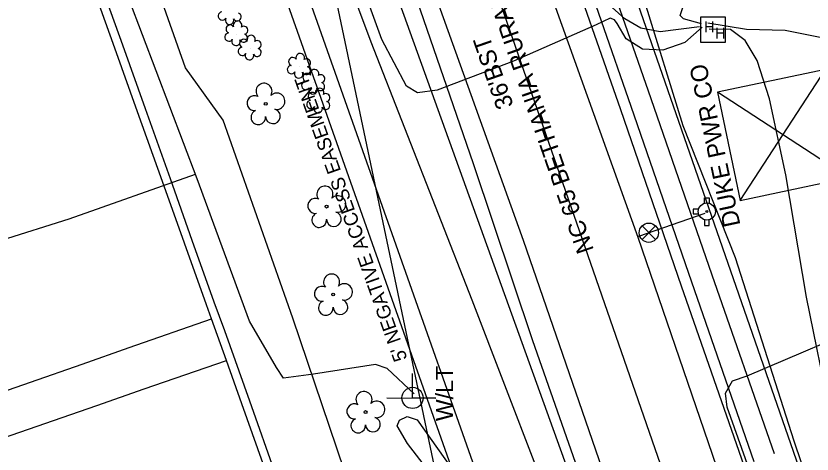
# Model space of a CAD drawing. Extents: x 1614611 to 1617571, y 898867 to 905462.
# Drawn here: x 1616147.3 to 1616331.4, y 903736.2 to 903837.4 of the extents above; entities that cross this region are included whole.
import ezdxf

# ---------------------------------------------------------------- set-up
doc = ezdxf.new("R2010")
doc.units = 0
for name, color, linetype in [('Exist Boundary Watershed Residential C 05', 7, 'Continuous'), ('Exist Other Culture Fence Line', 7, 'Continuous'), ('Exist Right of Way Easement Line Text', 7, 'Continuous'), ('Exist Roads Change in Surface', 7, 'Continuous'), ('Exist Roads EOP Text', 7, 'Continuous'), ('Exist Utilities Gas UG Line SUE LOS B', 7, 'Continuous'), ('Exist Utilities Power Joint Use Telephone CELL', 7, 'Continuous'), ('Exist Utilities Power Joint Use Telephone Text', 7, 'Continuous'), ('Exist Utilities Power Tower Text', 7, 'Continuous'), ('Exist Utilities Telephone Hand Hole CELL', 7, 'Continuous'), ('Exist Utilities Telephone UG Cable SUE LOS B', 7, 'Continuous'), ('Exist Utilities Telephone UG FO SUE LOS B', 7, 'Continuous'), ('Exist Utilities Telephone UG FO SUE LOS C', 7, 'Continuous'), ('Exist Utilities Water UG Line SUE LOS B', 7, 'Continuous'), ('Exist Vegetation Hedge Row', 7, 'Continuous'), ('Exist Vegetation Shrub CELL', 7, 'Continuous'), ('Exist Vegetation Tree CELL', 7, 'Continuous'), ('Prop Drainage Structure Catch Basin Grate 840 03E Label', 7, 'Continuous'), ('Prop Drainage Structure Drop Inlet In Approach Slab 840 13 CELL', 7, 'Continuous'), ('Prop Earthen Structure Base Ditch Detail CELL', 7, 'Continuous'), ('Prop Earthen Structure Cut Ditch Special Back of Curb Detail CELL', 7, 'Continuous'), ('Prop Earthen Structure Head Ditch Label', 7, 'Continuous'), ('Prop Earthen Structure V Ditch Detail Label', 7, 'Continuous'), ('Raster_Level_2', 7, 'Continuous'), ('Scratch_Level_1', 7, 'Continuous'), ('Scratch_Level_9', 7, 'Continuous')]:
    doc.layers.add(name, color=color, linetype=linetype)

# ---------------------------------------------------------------- blocks, each defined once
blk = doc.blocks.new('EXIST UTILITIES WATER FIRE HYDRANT')
at = {"layer": 'Prop Earthen Structure Base Ditch Detail CELL'}
blk.add_line((0, 0), (0, 0), dxfattribs=at)
for points in [[(-0.01025, 0.03825), (-0.01025, 0.064), (0.01025, 0.064), (0.01025, 0.03775)], [(-0.03825, 0.01025), (-0.064, 0.01025), (-0.064, -0.01025), (-0.03825, -0.01025)], [(-0.01025, -0.03825), (-0.01025, -0.064), (0.01025, -0.064), (0.01025, -0.03775)]]:
    blk.add_lwpolyline(points, dxfattribs=at)
for radius in [0.03954, 0.00485]:
    blk.add_circle((0, 0), radius, dxfattribs=at)
blk = doc.blocks.new('EXIST UTILITIES WATER VALVE')
at = {"layer": 'Prop Earthen Structure V Ditch Detail Label'}
blk.add_lwpolyline([(0.0315, 0.0315), (-0.0315, -0.0315), (0, 0), (0.0315, -0.0315), (-0.0315, 0.0315)], dxfattribs=at)
blk.add_circle((0, 0), 0.0445, dxfattribs=at)

msp = doc.modelspace()

# ---------------------------------------------------------------- linework, layer by layer
at = {"layer": 'Exist Boundary Watershed Residential C 05'}
for points in [[(1616117.86, 904294.32), (1616132.6, 904254.66), (1616147.03, 904215.59), (1616161.55, 904176.09), (1616175.82, 904137.25), (1616190.47, 904097.09), (1616204.98, 904057.33), (1616219.73, 904016.73), (1616233.88, 903976.63), (1616247.93, 903936.53), (1616261.75, 903896.6), (1616275.82, 903856.12), (1616289.5, 903816.57), (1616303.58, 903775.98), (1616318, 903734.48)], [(1616195.63, 903764.68), (1616193.18, 903771.3), (1616188.12, 903785.57), (1616183.07, 903799.8), (1616177.32, 903815.93), (1616172.04, 903830.68), (1616166.62, 903845.72)], [(1616228.55, 903499.67), (1616241.49, 903504.21), (1616254.35, 903508.75), (1616274.1, 903515.89), (1616283.18, 903519.23), (1616278.16, 903533.55), (1616272.29, 903550.22), (1616266.96, 903564.82), (1616261.52, 903580.04), (1616256.36, 903594.89), (1616250.78, 903610.5), (1616245.15, 903626.51), (1616239.64, 903641.51), (1616233.87, 903657.61), (1616228.87, 903671.59), (1616223.77, 903685.94), (1616218.3, 903701.18), (1616213.09, 903715.7), (1616207.52, 903731.14), (1616201.4, 903748.42), (1616195.63, 903764.68)]]:
    msp.add_lwpolyline(points, dxfattribs=at)
at = {"layer": 'Exist Other Culture Fence Line'}
for points in [[(1616211.35, 903767.58), (1616195.22, 903813.36), (1616186.56, 903825.42), (1616168.75, 903875.81), (1616153.63, 903916.5), (1616129.58, 903932.3), (1616098.05, 903952.43), (1616082.04, 903962.19), (1616045.01, 903949.52), (1616000.86, 903933.41), (1615934.86, 903910.4), (1615905.89, 903899.71)], [(1616340.29, 903264.26), (1616332.08, 903290.24), (1616316.67, 903338.32), (1616302.47, 903379.06), (1616267.37, 903366.34), (1616220.02, 903349.18), (1616202.8, 903398.78), (1616185.25, 903447.61), (1616177.66, 903469.59), (1616182.75, 903471.48), (1616219.13, 903484.56), (1616299.32, 903513.96), (1616290.54, 903538.93), (1616272.63, 903588.03), (1616251.39, 903649.78), (1616231.78, 903707.31), (1616211.35, 903767.58)]]:
    msp.add_lwpolyline(points, dxfattribs=at)
at = {"layer": 'Exist Roads Change in Surface'}
for points in [[(1615977.86, 903692.4), (1616012.69, 903704.67), (1616058.14, 903720.5), (1616081.62, 903728.6), (1616102.28, 903735.77), (1616138.67, 903748.68), (1616162.62, 903756.97), (1616173.49, 903760.81), (1616192.57, 903767.41)], [(1615981.36, 903682.64), (1616016.19, 903695.14), (1616061.6, 903710.95), (1616085.09, 903719.1), (1616105.67, 903726.37), (1616142.12, 903739.16), (1616166.07, 903747.45), (1616176.95, 903751.26), (1616196.01, 903757.85)]]:
    msp.add_lwpolyline(points, dxfattribs=at)
at = {"layer": 'Exist Utilities Gas UG Line SUE LOS B'}
msp.add_lwpolyline([(1616574.94, 902856.71), (1616560.06, 902902.39), (1616552.18, 902925.27), (1616536.08, 902973.65), (1616521.52, 903015.88), (1616492.41, 903100.65), (1616481.17, 903130.4), (1616470.48, 903162.66), (1616450.18, 903220.6), (1616431.22, 903276.51), (1616418.49, 903313.39), (1616364.61, 903464.71), (1616350.51, 903509.73), (1616310.55, 903618.21), (1616275.13, 903713.81), (1616252.85, 903771.73), (1616229.48, 903831.39), (1616218.51, 903860.65), (1616218.15, 903861.58), (1616200.49, 903922.94), (1616158.51, 904013.15), (1616156.79, 904018.63), (1616125.02, 904117.19), (1616112.76, 904150.51)], dxfattribs=at)
at = {"layer": 'Exist Utilities Power Joint Use Telephone CELL'}
msp.add_line((1616239.05, 903749.18), (1616239.05, 903749.18), dxfattribs=at)
msp.add_lwpolyline([(1616233.11, 903749.18), (1616244.45, 903749.14), (1616239.05, 903749.16), (1616239.05, 903754.8)], dxfattribs=at)
msp.add_circle((1616239.05, 903749.18), 2.45, dxfattribs=at)
at = {"layer": 'Exist Utilities Telephone Hand Hole CELL'}
for p, q in [((1616305.68, 903837.13), (1616305.68, 903831.4)), ((1616311.41, 903837.13), (1616305.68, 903837.13)), ((1616311.41, 903831.4), (1616311.41, 903837.13)), ((1616308.55, 903834.26), (1616308.55, 903834.26)), ((1616305.68, 903831.4), (1616311.41, 903831.4))]:
    msp.add_line(p, q, dxfattribs=at)
at = {"layer": 'Exist Utilities Telephone UG Cable SUE LOS B'}
for points in [[(1616341.13, 903526.17), (1616350.06, 903524.57), (1616353.18, 903523.97), (1616354.27, 903525.62), (1616354.2, 903527.32), (1616352.41, 903531.49), (1616346.51, 903551.88), (1616338.38, 903572.73), (1616311.12, 903649.59), (1616299.64, 903684.42), (1616264.73, 903785.56), (1616225.23, 903895.34)], [(1616373.87, 903568.46), (1616374.3, 903569.41), (1616373.86, 903570.39), (1616361.62, 903602.86), (1616341.95, 903659.09), (1616330.11, 903695.59), (1616311.83, 903747.03), (1616311.46, 903750.28), (1616313.05, 903753.14), (1616316.41, 903754.31), (1616347.19, 903767.38), (1616362.66, 903772.42), (1616371.42, 903776.41)]]:
    msp.add_lwpolyline(points, dxfattribs=at)
at = {"layer": 'Exist Utilities Telephone UG FO SUE LOS B'}
for points in [[(1616305.86, 903835.58), (1616301.71, 903836.75), (1616300.93, 903837.51), (1616301.7, 903839.81), (1616304.58, 903843.5), (1616306.34, 903849.92), (1616306.68, 903889.95), (1616304.63, 903908.72), (1616293.63, 903957.65), (1616274.72, 904023.16), (1616260.11, 904069.82), (1616245.31, 904104.27), (1616231.41, 904145.88), (1616215.41, 904195.22), (1616204.68, 904240.22), (1616199.33, 904261.21), (1616183.55, 904304.43), (1616162.6, 904355.73), (1616148.58, 904401.99), (1616136.38, 904433.35), (1616120.49, 904476.41), (1616105.61, 904520.44), (1616089.41, 904571.33)], [(1616305.43, 903834.95), (1616296.33, 903833.77), (1616291.87, 903834.62), (1616288.13, 903836.73), (1616285.25, 903839.39), (1616277.28, 903853.64), (1616262.51, 903895.33), (1616243.28, 903949.17), (1616237.33, 903966.37), (1616227.47, 903998.34)], [(1616306.02, 903834.81), (1616302.03, 903831.29), (1616296.93, 903829.49), (1616292.25, 903829.78), (1616288.46, 903832.16), (1616286.38, 903835.67), (1616285.77, 903836.54), (1616284.73, 903836.89), (1616281.51, 903835.36), (1616262.41, 903826.99), (1616244.75, 903820.26), (1616240.16, 903819.66), (1616237.67, 903821.17), (1616231.95, 903831.99), (1616208.49, 903896.38)], [(1616413.77, 903500.18), (1616402.08, 903534.75), (1616383.28, 903584.85), (1616378.31, 903598.68), (1616360.02, 903639.24), (1616356.39, 903655.99), (1616340.68, 903699.57), (1616327.33, 903739.18), (1616327.34, 903739.18), (1616313.72, 903781.55), (1616301.65, 903812.03), (1616292.8, 903840.69)], [(1616307.37, 903835.83), (1616316.28, 903834.41), (1616325.26, 903834.16), (1616333.69, 903832.44), (1616339.08, 903829.17), (1616355.03, 903804.45), (1616367.18, 903789.49), (1616372.35, 903777.82)], [(1616367.72, 903663.9), (1616363.6, 903662.09), (1616361.25, 903662.79), (1616358.51, 903666.15), (1616344.89, 903713.16), (1616335.76, 903744.87), (1616330.15, 903772.43), (1616325.41, 903800.74), (1616321.6, 903818.31), (1616318.76, 903827.11), (1616315.94, 903831.79), (1616312.59, 903834.29), (1616307.67, 903834.34)]]:
    msp.add_lwpolyline(points, dxfattribs=at)
at = {"layer": 'Exist Utilities Telephone UG FO SUE LOS C'}
msp.add_lwpolyline([(1616279.08, 903721.31), (1616179.5, 903997.15), (1616170.18, 904002.27)], dxfattribs=at)
at = {"layer": 'Exist Utilities Water UG Line SUE LOS B'}
msp.add_line((1616306.62, 903791.8), (1616291.31, 903786.5), dxfattribs=at)
msp.add_lwpolyline([(1616526.94, 903118.95), (1616504.59, 903181.23), (1616480.02, 903252.46), (1616446.17, 903345), (1616411.28, 903445.17), (1616385.62, 903515.15), (1616350.02, 903616.87), (1616323.73, 903691.37), (1616291.21, 903786.26), (1616260.45, 903872.07), (1616224.66, 903974.02), (1616192.08, 904066.13), (1616173.94, 904118.11), (1616130.42, 904237.78), (1616097.26, 904331.65), (1616083.48, 904374.45), (1616069.85, 904420.53), (1616059.14, 904458.49), (1616050.85, 904496.39), (1616045.84, 904527.76), (1616030.28, 904669.9)], dxfattribs=at)
at = {"layer": 'Exist Vegetation Hedge Row'}
msp.add_lwpolyline([(1616244.1, 903730.53), (1616237.85, 903738.68), (1616235.5, 903742.71), (1616236, 903744), (1616237.79, 903744.91), (1616240.15, 903744.1), (1616247.84, 903733.22)], dxfattribs=at)
at = {"layer": 'Exist Vegetation Shrub CELL'}
for p, q in [((1616198.36, 903833.24), (1616198.36, 903833.24)), ((1616201.48, 903829.93), (1616201.48, 903829.93)), ((1616212.84, 903825.73), (1616212.84, 903825.73)), ((1616216.15, 903822.05), (1616216.15, 903822.05)), ((1616217.33, 903817.68), (1616217.33, 903817.68))]:
    msp.add_line(p, q, dxfattribs=at)
for centre, radius, start, end in [((1616195.06, 903837.42), 0.955, 95.1099, 327.9534), ((1616198.5, 903837.19), 0.937, 204.9913, 73.4601), ((1616196.73, 903836.44), 0.984, 151.2797, 21.387), ((1616198.59, 903835.28), 0.99, 334.8391, 200.4717), ((1616196.88, 903834.37), 0.968, 35.8908, 245.4216), ((1616200.03, 903834.11), 0.929, 284.4567, 126.0861), ((1616196.56, 903832.54), 0.955, 95.1099, 327.9534), ((1616200, 903832.31), 0.937, 204.9913, 73.4601), ((1616201.71, 903831.97), 0.99, 334.8391, 200.4717), ((1616198.23, 903831.56), 0.984, 151.2797, 21.387), ((1616200, 903831.06), 0.968, 35.8908, 245.4216), ((1616203.15, 903830.8), 0.929, 284.4567, 126.0861), ((1616199.68, 903829.23), 0.955, 95.1099, 327.9534), ((1616203.12, 903829), 0.937, 204.9913, 73.4601), ((1616201.35, 903828.25), 0.984, 151.2797, 21.387), ((1616211.36, 903826.86), 0.968, 35.8908, 245.4216), ((1616213.07, 903827.77), 0.99, 334.8391, 200.4717), ((1616214.51, 903826.6), 0.929, 284.4567, 126.0861), ((1616211.04, 903825.03), 0.955, 95.1099, 327.9534), ((1616214.48, 903824.8), 0.937, 204.9913, 73.4601), ((1616212.71, 903824.05), 0.984, 151.2797, 21.387), ((1616214.67, 903823.18), 0.968, 35.8908, 245.4216), ((1616216.38, 903824.09), 0.99, 334.8391, 200.4717), ((1616217.83, 903822.92), 0.929, 284.4567, 126.0861), ((1616214.35, 903821.35), 0.955, 95.1099, 327.9534), ((1616217.79, 903821.12), 0.937, 204.9913, 73.4601), ((1616215.85, 903818.81), 0.968, 35.8908, 245.4216), ((1616216.03, 903820.37), 0.984, 151.2797, 21.387), ((1616217.56, 903819.72), 0.99, 334.8391, 200.4717), ((1616215.53, 903816.98), 0.955, 95.1099, 327.9534), ((1616219.01, 903818.55), 0.929, 284.4567, 126.0861), ((1616217.21, 903816), 0.984, 151.2797, 21.387), ((1616218.97, 903816.76), 0.937, 204.9913, 73.4601)]:
    msp.add_arc(centre, radius, start, end, dxfattribs=at)
at = {"layer": 'Exist Vegetation Tree CELL'}
for p, q in [((1616205.09, 903817.14), (1616205.09, 903817.14)), ((1616219.18, 903793.38), (1616219.18, 903793.38)), ((1616220.71, 903773.07), (1616220.71, 903773.07)), ((1616228.2, 903745.92), (1616228.2, 903745.92))]:
    msp.add_line(p, q, dxfattribs=at)
for centre in [(1616205.09, 903817.14), (1616219.18, 903793.38), (1616220.71, 903773.07), (1616228.2, 903745.92)]:
    msp.add_circle(centre, 0.326, dxfattribs=at)
for centre, radius, start, end in [((1616204.71, 903820.01), 1.86, 330.1651, 219.7134), ((1616207.64, 903817.72), 1.9, 257.1011, 134.1999), ((1616202.48, 903817.29), 1.73, 62.6636, 279.3457), ((1616203.39, 903814.01), 1.69, 111.5671, 6.231), ((1616206.76, 903814.24), 1.7, 181.2822, 74.56), ((1616218.79, 903796.25), 1.86, 330.1651, 219.7134), ((1616221.73, 903793.96), 1.9, 257.1011, 134.1999), ((1616216.57, 903793.53), 1.73, 62.6636, 279.3457), ((1616220.85, 903790.48), 1.7, 181.2822, 74.56), ((1616217.47, 903790.25), 1.69, 111.5671, 6.231), ((1616220.32, 903775.94), 1.86, 330.1651, 219.7134), ((1616223.26, 903773.66), 1.9, 257.1011, 134.1999), ((1616218.1, 903773.22), 1.73, 62.6636, 279.3457), ((1616222.38, 903770.17), 1.7, 181.2822, 74.56), ((1616219, 903769.95), 1.69, 111.5671, 6.231), ((1616227.82, 903748.79), 1.86, 330.1651, 219.7134), ((1616225.6, 903746.07), 1.73, 62.6636, 279.3457), ((1616230.75, 903746.51), 1.9, 257.1011, 134.1999), ((1616226.5, 903742.8), 1.69, 111.5671, 6.231), ((1616229.88, 903743.02), 1.7, 181.2822, 74.56)]:
    msp.add_arc(centre, radius, start, end, dxfattribs=at)
at = {"layer": 'Prop Drainage Structure Catch Basin Grate 840 03E Label'}
for points in [[(1616216.11, 903754.65), (1616209.18, 903753.77), (1616207.59, 903756.18), (1616201.31, 903766.89), (1616189.22, 903799.82), (1616173.47, 903841.46), (1616167.39, 903860.41), (1616167.16, 903861.99), (1616154.51, 903899.58), (1616149.01, 903912.2)], [(1616188.81, 903800.81), (1616159.54, 903790.47), (1616143.92, 903785.53), (1616125.62, 903780.42), (1616107.73, 903774.01), (1616106.42, 903773.68), (1616075.03, 903763.65), (1616039.24, 903750.83), (1616002.72, 903737.28), (1615981.14, 903729.78)], [(1616239.41, 903750.09), (1616233.18, 903755.96), (1616230.51, 903756.88), (1616216.11, 903754.65)]]:
    msp.add_lwpolyline(points, dxfattribs=at)
at = {"layer": 'Prop Drainage Structure Drop Inlet In Approach Slab 840 13 CELL'}
msp.add_lwpolyline([(1616314.85, 903794.79), (1616339.85, 903800.09), (1616334.54, 903825.08), (1616309.55, 903819.78), (1616314.85, 903794.79), (1616334.54, 903825.08), (1616339.85, 903800.09), (1616309.55, 903819.78)], dxfattribs=at)
at = {"layer": 'Prop Earthen Structure Cut Ditch Special Back of Curb Detail CELL'}
msp.add_lwpolyline([(1616323.1, 903521.01), (1616157.44, 903989.53)], dxfattribs=at)
at = {"layer": 'Prop Earthen Structure Head Ditch Label'}
msp.add_line((1615887.44, 905426.15), (1616864.55, 900788.06), dxfattribs=at)
for points in [[(1616327.81, 903522.67), (1616162.16, 903991.19)], [(1616358.79, 903645.91), (1616266.57, 903911.08), (1616266.56, 903911.09)]]:
    msp.add_lwpolyline(points, dxfattribs=at)
at = {"layer": 'Raster_Level_2'}
msp.add_line((1616565.11, 902961.33), (1616239.34, 903898.04), dxfattribs=at)
at = {"layer": 'Scratch_Level_1'}
for points in [[(1616122.43, 904296.46), (1616137.34, 904256.3), (1616151.63, 904217.58), (1616166.45, 904177.4), (1616180.52, 904139.04), (1616195.16, 904098.73), (1616209.58, 904059.11), (1616224.45, 904018.46), (1616238.58, 903978.47), (1616252.68, 903938.24), (1616266.45, 903898.41), (1616280.47, 903857.78), (1616294.14, 903818.38), (1616308.3, 903777.63), (1616322.66, 903736.35)], [(1616191.39, 903770.68), (1616186.32, 903784.93), (1616181.22, 903799.14), (1616175.48, 903815.27), (1616170.2, 903830.02), (1616164.78, 903845.06)], [(1616236.41, 903644.88), (1616233.01, 903654.38), (1616232.08, 903656.97), (1616227.07, 903670.95), (1616221.98, 903685.3), (1616216.51, 903700.53), (1616211.3, 903715.06), (1616205.72, 903730.5), (1616199.6, 903747.78), (1616196.01, 903757.85), (1616192.57, 903767.41), (1616191.39, 903770.68)]]:
    msp.add_lwpolyline(points, dxfattribs=at)
at = {"layer": 'Scratch_Level_9'}
for points in [[(1616115.61, 904293.45), (1616130.22, 904253.88), (1616144.71, 904214.78), (1616159.36, 904175.17), (1616173.54, 904136.33), (1616188.19, 904096.22), (1616202.56, 904056.51), (1616217.36, 904015.9), (1616231.52, 903975.89), (1616245.62, 903935.7), (1616259.38, 903895.73), (1616273.35, 903855.36), (1616287.12, 903815.79), (1616301.21, 903775.08), (1616315.66, 903733.58)], [(1616182.37, 904002.15), (1616180.78, 904001.18), (1616182.71, 903996.46), (1616196.01, 903962.82), (1616210.69, 903923.18), (1616225.09, 903883.2), (1616239.3, 903843.39), (1616253.05, 903803.36), (1616266.79, 903762.41), (1616281.33, 903720.95)]]:
    msp.add_lwpolyline(points, dxfattribs=at)

# ---------------------------------------------------------------- block references
at = {"layer": 'Prop Earthen Structure Base Ditch Detail CELL', "xscale": 50, "yscale": 50}
msp.add_blockref('EXIST UTILITIES WATER FIRE HYDRANT', (1616307.11, 903792.24), dxfattribs=at)
at = {"layer": 'Prop Earthen Structure V Ditch Detail Label', "xscale": 50, "yscale": 50}
msp.add_blockref('EXIST UTILITIES WATER VALVE', (1616293.69, 903787.34), dxfattribs=at)

# ---------------------------------------------------------------- texts
at = {"layer": 'Exist Right of Way Easement Line Text'}
msp.add_text("5' NEGATIVE ACCESS EASEMENT", height=3.2, rotation=109.4723, dxfattribs=at).set_placement((1616237.89, 903758.25))
at = {"layer": 'Exist Roads EOP Text'}
for s, p in [('NC 65 BETHANIA RURAL HALL RD.', (1616281.02, 903783.38)), ("36'BST", (1616262.46, 903816.73))]:
    msp.add_text(s, height=4, rotation=109.1948, dxfattribs=at).set_placement(p)
at = {"layer": 'Exist Utilities Power Joint Use Telephone Text'}
msp.add_text('W/LT', height=4, rotation=90, dxfattribs=at).set_placement((1616248.44, 903743.8))
at = {"layer": 'Exist Utilities Power Tower Text'}
msp.add_text('DUKE PWR CO', height=4, rotation=101.9854, dxfattribs=at).set_placement((1616314.9, 903789.13))
at = {"layer": 'Exist Utilities Telephone Hand Hole CELL'}
for p in [(1616306.46, 903833.67), (1616309.03, 903832.21)]:
    msp.add_text('H', height=2.5, dxfattribs=at).set_placement(p)

doc.saveas('drawing.dxf')
